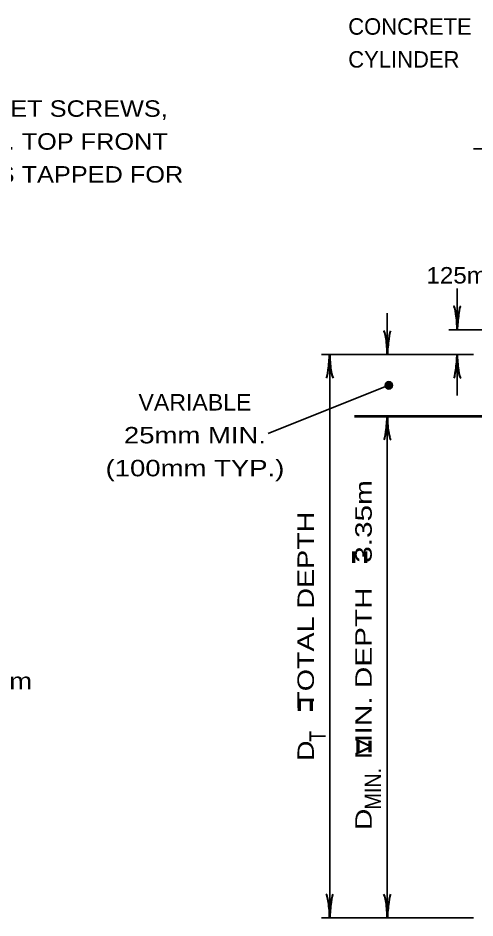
# Model space of a CAD drawing. Extents: x -35 to 821, y -13 to 531.
# Drawn here: x 455.8 to 522.5, y 281.2 to 412.5 of the extents above; entities that cross this region are included whole.
import ezdxf
from ezdxf.enums import TextEntityAlignment as Align

# ---------------------------------------------------------------- set-up
doc = ezdxf.new("R2010")
doc.units = 0
doc.header["$LTSCALE"] = 0.96
doc.layers.add('1', color=7, linetype='Continuous', lineweight=53)

msp = doc.modelspace()

# ---------------------------------------------------------------- hatches: boundary and pattern name
at = {"layer": '1'}
msp.add_hatch(color=256, dxfattribs=at).paths.add_polyline_path([(510.4668, 358.9575, 1), (509.3876, 358.9575, 1)])

# ---------------------------------------------------------------- linework, layer by layer
at = {"layer": '1', "lineweight": 35}
for p, q in [((519.9048, 367.0595), (519.9048, 373.0595)), ((509.7048, 363.4595), (509.7048, 369.4595)), ((528.3048, 367.0595), (518.7048, 367.0595)), ((522.3048, 363.4595), (500.1048, 363.4595)), ((501.3048, 363.4595), (501.3048, 281.2595)), ((519.9048, 363.4595), (519.9048, 357.4595)), ((509.9272, 358.9575), (492.3513, 351.9249)), ((509.7048, 354.4595), (509.7048, 281.2595)), ((522.3048, 281.2595), (500.1048, 281.2595))]:
    msp.add_line(p, q, dxfattribs=at)
at = {"layer": '1'}
msp.add_line((504.9048, 354.4595), (523.5048, 354.4595), dxfattribs=at)
at = {"layer": '1', "lineweight": 35}
msp.add_lwpolyline([(532.5048, 393.4595), (528.3048, 393.4595), (522.3048, 393.4595)], dxfattribs=at)
msp.add_circle((509.9272, 358.9575), 0.5396, dxfattribs=at)
at = {"layer": '1', "lineweight": 40}
for centre, major_axis, ratio, start_param, end_param in [((519.5732, 368.3689), (0.1874, -2.1428), 0.122415, 0.89635335, 3.14159265), ((520.1587, 368.4041), (-0.2108, -2.1077), 0.07063, 3.14071475, 5.41810995), ((509.3732, 364.7689), (0.1874, -2.1428), 0.122415, 0.89635335, 3.14159265), ((509.9587, 364.8041), (-0.2108, -2.1077), 0.07063, 3.14071475, 5.41810995), ((501.0509, 362.1149), (0.2108, 2.1077), 0.07063, 3.14071475, 5.41810995), ((501.0509, 362.1149), (0.2108, 2.1077), 0.07063, 3.14071475, 5.41810995), ((501.6364, 362.1501), (-0.1874, 2.1428), 0.122415, 0.89635335, 3.14159265), ((501.6364, 362.1501), (-0.1874, 2.1428), 0.122415, 0.89635335, 3.14159265), ((519.6509, 362.1149), (0.2108, 2.1077), 0.07063, 3.14071475, 5.41810995), ((520.2364, 362.1501), (-0.1874, 2.1428), 0.122415, 0.89635335, 3.14159265), ((509.4509, 353.1149), (0.2108, 2.1077), 0.07063, 3.14071475, 5.41810995), ((510.0364, 353.1501), (-0.1874, 2.1428), 0.122415, 0.89635335, 3.14159265), ((500.9732, 282.5689), (0.1874, -2.1428), 0.122415, 0.89635335, 3.14159265), ((501.5587, 282.6041), (-0.2108, -2.1077), 0.07063, 3.14071475, 5.41810995), ((509.3732, 282.5689), (0.1874, -2.1428), 0.122415, 0.89635335, 3.14159265), ((509.9587, 282.6041), (-0.2108, -2.1077), 0.07063, 3.14071475, 5.41810995)]:
    msp.add_ellipse(centre, major_axis=major_axis, ratio=ratio, start_param=start_param, end_param=end_param, dxfattribs=at)

# ---------------------------------------------------------------- texts
at = {"layer": '1'}
for s, p in [('CONCRETE', (504.0091, 410.1046)), ('CYLINDER', (504.0091, 405.3046))]:
    msp.add_text(s, height=2.4, dxfattribs=at).set_placement(p)
for s, width, p in [('CAPS WITH SET SCREWS,', 1.15, (430.7292, 398.1305)), ('ALL CHORDS. TOP FRONT', 1.15, (430.7292, 393.3305)), ('CHORD CAPS TAPPED FOR', 1.15, (430.7292, 388.5305)), ('125mm', 1.1, (515.4131, 373.808)), ('254.0mm', 1.25, (441.1765, 314.6183))]:
    msp.add_text(s, height=2.4, dxfattribs=dict(at, width=width)).set_placement(p)
for s, width, p in [('VARIABLE', 1.05, (481.6503, 355.2804)), ('25mm MIN.', 1.25, (481.6503, 350.4804)), ('(100mm TYP.)', 1.25, (481.6503, 345.6804))]:
    msp.add_text(s, height=2.4, dxfattribs=dict(at, width=width)).set_placement(p, align=Align.CENTER)
for s, height, width, p in [('D      MIN. DEPTH   3.35m', 2.4, 1.35, (507.4372, 294.0794)), ('D    TOTAL DEPTH', 2.4, 1.3, (499.0031, 304.1288)), ('=', 4.8, 0.55, (507.9671, 332.8419)), ('=', 4.8, 0.55, (500.0351, 311.26)), ('T', 2.4, 0.8, (500.7396, 306.9824)), ('=', 4.8, 0.55, (508.6016, 305.2297)), ('MIN.', 2.4, 0.9, (508.8014, 297.057))]:
    msp.add_text(s, height=height, rotation=90, dxfattribs=dict(at, width=width)).set_placement(p)

doc.saveas('drawing.dxf')
